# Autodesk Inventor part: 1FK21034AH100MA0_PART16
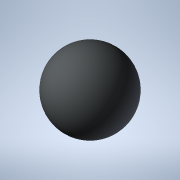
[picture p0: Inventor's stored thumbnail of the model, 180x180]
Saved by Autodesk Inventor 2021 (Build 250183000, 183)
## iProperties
Created: 2025-04
Part Number: 1FK21034AH100MA0_PART16
Material: Generic
Catalog Web Link: www.3dfindit.com
Description: -Servo synchronous motor
Document SubType Name: Modeling
Designer: psAdmin
Mass: 0.113097 g
Surface Area: 1.13097 cm^2
Volume: 0.113097 cm^3
Density: 1 g/cm^3
Appearance: PSOLRGB-212-217-219
Category: PARTsolutions
Title: 1FK21034AH100MA0_PART16
Author: Cadenas PARTsolutions
Comments: Servo synchronous motor
Sending System: PARTsolutions
Preprocessor: ST-DEVELOPER v19.3
PSOL_IDENT_0: {$CADENAS_DATA/23d-libs/siemens_ag/_cat_/39/97/1fk21034ah100ma0.prj},216 {VTYP=3D},{NB=1FK21034AH100
PSOL_IDENT_1: MA0_PART16},{LINA=1FK21034AH100MA0_PART16},{NN=1FK21034AH100MA0_PART16},{NOPRJ=TRUE},{DATE=19.08.202
PSOL_IDENT_2: 5 14:00:33},{GEOMDATE=30.07.2025 02:02:21},{VERSION=},{LINEID=10},{WBVAR=},{WBNUMERIC=}  {NB=1FK2103
PSOL_IDENT_3: 4AH100MA0_PART16},{LINA=1FK21034AH100MA0_PART16},{KT=DUMMY},{PREVIEW=../../../_pool_/d3/78/p_d211_xx
PSOL_IDENT_4: _00934j.png},{DESCSHORT=SIMOTICS S-1FK2 HD, SINAMICS S210 3AC 400V-480V, 1.01 Nm, 4500 rpm},{DESCLON
PSOL_IDENT_5: G=SIMOTICS S-1FK2 HD servo motor M0=1.27 Nm; PN = 0.48 kW at nN=4500 rpm (380-480 V); PN = 0.3 kW at
PSOL_IDENT_6: nN=2500 rpm (200-240 V); with holding brake; degree of protection IP64; cylindrical shaft D14 x 30
PSOL_IDENT_7: mm; absolute encoder 22-bit + 12-bit multiturn (encoder AM22DQC); with OCC interface; plug size M17,
PSOL_IDENT_8: rotatable; SIMOTICS S-1FK2 servomotorfor a wide range of uses in industrial environments. SIMOTICS
PSOL_IDENT_9: S‑1FK2 servomotors are compact synchronous motors with a high dynamic performance that set themselve
PSOL_IDENT_10: s apart as a result of their high power density, degree of protection and overload capability. The m
PSOL_IDENT_11: otors are available in two variants: as High Dynamic variant (highest dynamic performance as a resul
PSOL_IDENT_12: t of the low intrinsic moment of inertia for applications demanding a high dynamic performance with
PSOL_IDENT_13: low moved masses) - and as Compact variant (precise and stable closed-loop control for medium up to
PSOL_IDENT_14: large moved masses as a result of a medium intrinsic moment of inertia). SIMOTICSS‑1FK2 servomotors
PSOL_IDENT_15: fully exploit their strengths in a system with the SINAMICSS210 frequency converter and simple conne
PSOL_IDENT_16: ction using the one cable connection (OCC). Advantages include the short control and positioning tim
PSOL_IDENT_17: es, fast and precise correction of disturbing quantities as well as stable control with a high dynam
PSOL_IDENT_18: ic performance. The servo motors can be configured to address a wide range of requirements. For exam
PSOL_IDENT_19: ple with and without holding brake, IP64 or IP65 degree of protection, singleturn or multiturn absol
PSOL_IDENT_20: ute encoders - to name just a few. Further, the servomotors are available in different shaft heights
PSOL_IDENT_21: extending from 20 to 100. A shaft sealing ring is available to achieve an IP65 degree of protection
PSOL_IDENT_22: and for subsequent mounting at the motor or as spare part. SIMOTICS - the optimum motor for each an
PSOL_IDENT_23: d every motion control application.},{INTNO=195125454019},{SUPPLIERALTNO=1FK2103-4AH10-0MA0},{MANUID=
PSOL_IDENT_24: 1FK21034AH100MA0},{MANUNAME=Siemens},{MANUTYPEDESC=SYNCHRONOUS MOTOR 1FK2 HD 1,27 NM},{AAU732=SIMOTI
PSOL_IDENT_25: CS},{AAO057=S-1FK2},{AAU734=SIMOTICS S-1FK2 HD servo motor M0=1.27 Nm; PN = 0.48 kW at nN=4500 rpm (
PSOL_IDENT_26: 380-480 V); PN = 0.3 kW at nN=2500 rpm (200-240 V); with holding brake; degree of protection IP64; c
PSOL_IDENT_27: ylindrical shaft D14 x 30 mm; absolute encoder 22-bit + 12-bit multiturn (encoder AM22DQC); with OCC
PSOL_IDENT_28: interface; plug size M17, rotatable;},{AAW338=SYNCHRONOUS MOTOR 1FK2 HD 1,27 NM},{AAO742=SIMOTICS},
PSOL_IDENT_29: {AAO663=4034106444921},{NOCUPEROU=1},{PRICEQUANTITY=1},{QUANTITYMIN=1},{QUANTITYINT=1},{CTN=85015100
PSOL_IDENT_30: },{COO=RO},{AAO676=1FK2103-4AH10-0MA0},{AAO677=Siemens AG},{ORDERUNIT=C62},{CONTENTUNIT=C62}
NB: 1FK21034AH100MA0_PART16
NT: Servo synchronous motor
NBSYN: $MANUID._PART16
LINA: 1FK21034AH100MA0_PART16
CATALOG: SIEMENS
PREVIEW: ../../../_pool_/d3/78/p_d211_xx_00934j.png
DESCSHORT: SIMOTICS S-1FK2 HD, SINAMICS S210 3AC 400V-480V, 1.01 Nm, 4500 rpm
DESCLONG: SIMOTICS S-1FK2 HD servo motor M0=1.27 Nm; PN = 0.48 kW at nN=4500 rpm (380-480 V); PN = 0.3 kW at nN=2500 rpm (200-240 V); with holding brake; degree of protec
INTNO: 195125454019
SUPPLIERALTNO: 1FK2103-4AH10-0MA0
MANUID: 1FK21034AH100MA0
MANUNAME: Siemens
MANUTYPEDESC: SYNCHRONOUS MOTOR 1FK2 HD 1,27 NM
AAU732: SIMOTICS
AAO057: S-1FK2
AAU734: SIMOTICS S-1FK2 HD servo motor M0=1.27 Nm; PN = 0.48 kW at nN=4500 rpm (380-480 V); PN = 0.3 kW at nN=2500 rpm (200-240 V); with holding brake; degree of protec
AAW338: SYNCHRONOUS MOTOR 1FK2 HD 1,27 NM
AAO742: SIMOTICS
AAO663: 4034106444921.0
NOCUPEROU: 1
PRICEQUANTITY: 1
QUANTITYMIN: 1
QUANTITYINT: 1
CTN: 85015100
COO: RO
ARTICLENO: 1FK21034AH100MA0_PART16
BOMINFO: 1FK21034AH100MA0_PART16
CREATOR: CADENAS GmbH
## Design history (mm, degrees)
feature "2025_04_17_15_09_00_0361"
body "Solid1"
